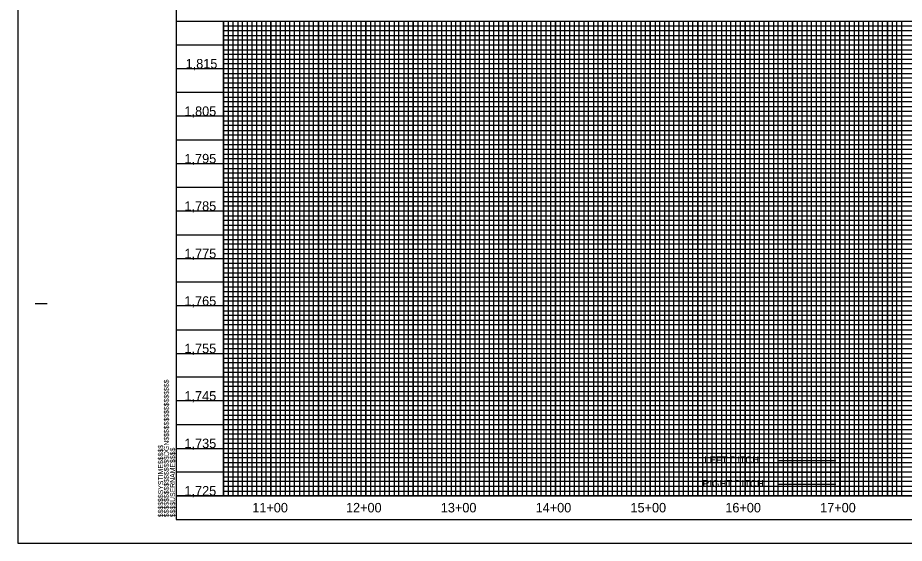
# Model space of a CAD drawing. Extents: x 502400 to 509344, y 448070 to 484209.
# Drawn here: x 505602 to 506537, y 483109 to 483662 of the extents above; entities that cross this region are included whole.
import ezdxf

# ---------------------------------------------------------------- set-up
doc = ezdxf.new("R2010")
doc.units = 0
for name, color, linetype in [('Exist Vertical Profile Vertical Axis Label', 7, 'Continuous'), ('Prop Grid Mask', 7, 'Continuous'), ('Prop PFL Ditch Label CELL', 7, 'Continuous'), ('Prop Vertical Profile Ditch Grade Left', 7, 'Continuous'), ('Sheet Layout Profile Border Port 2', 7, 'Continuous'), ('Sheet Plot Border Outside CELL', 7, 'Continuous'), ('Sheet Profile CELL', 7, 'Continuous'), ('Sheet Profile Grid Major CELL', 7, 'Continuous'), ('Sheet Profile Grid Middle CELL', 7, 'Continuous'), ('Sheet Profile Grid Minor CELL', 7, 'Continuous')]:
    doc.layers.add(name, color=color, linetype=linetype)

msp = doc.modelspace()

# ---------------------------------------------------------------- linework, layer by layer
at = {"layer": 'Prop Grid Mask'}
for points in [[(506319.18, 483208.71), (506469.18, 483208.71), (506469.18, 483183.71), (506319.18, 483183.71)], [(506319.18, 483183.71), (506469.18, 483183.71), (506469.18, 483158.71), (506319.18, 483158.71)]]:
    msp.add_lwpolyline(points, close=True, dxfattribs=at)
at = {"layer": 'Prop PFL Ditch Label CELL'}
for p, q in [((506404.73, 483171.06), (506464.73, 483171.06)), ((506319.18, 483168.71), (506319.18, 483168.71))]:
    msp.add_line(p, q, dxfattribs=at)
at = {"layer": 'Prop Vertical Profile Ditch Grade Left'}
msp.add_line((506404.73, 483196.06), (506464.73, 483196.06), dxfattribs=at)
at = {"layer": 'Sheet Layout Profile Border Port 2'}
msp.add_lwpolyline([(505819.08, 483658.71), (506619.08, 483658.71), (506619.08, 483158.71), (505819.08, 483158.71)], close=True, dxfattribs=at)
at = {"layer": 'Sheet Plot Border Outside CELL'}
msp.add_lwpolyline([(505602.08, 483108.71), (507286.08, 483108.71), (507286.08, 484208.71), (505602.08, 484208.71)], close=True, dxfattribs=at)
at = {"layer": 'Sheet Profile CELL'}
for p, q in [((505769.08, 483658.71), (507269.08, 483658.71)), ((505620.58, 483361.21), (505633.08, 483361.21)), ((507269.08, 483158.71), (505769.08, 483158.71)), ((505769.08, 483133.71), (507269.08, 483133.71)), ((505769.08, 483133.71), (505769.08, 483133.71)), ((505769.08, 483133.71), (505769.08, 483133.71)), ((505769.08, 483133.71), (505769.08, 483133.71)), ((505769.08, 483133.71), (505769.08, 483133.71)), ((505769.08, 483133.71), (505769.08, 483133.71)), ((505769.08, 483133.71), (505769.08, 483133.71)), ((505769.08, 483133.71), (505769.08, 483133.71))]:
    msp.add_line(p, q, dxfattribs=at)
msp.add_lwpolyline([(507269.08, 484183.71), (505769.08, 484183.71), (505769.08, 483133.71), (507269.08, 483133.71)], close=True, dxfattribs=at)
msp.add_lwpolyline([(505806.58, 483133.71), (505806.58, 483133.71)], dxfattribs=at)
at = {"layer": 'Sheet Profile Grid Major CELL'}
for p, q in [((506269.08, 483658.71), (506319.08, 483658.71)), ((506369.08, 483658.71), (506419.08, 483658.71)), ((506469.08, 483658.71), (506519.08, 483658.71))]:
    msp.add_line(p, q, dxfattribs=at)
for points in [[(505769.08, 483658.71), (505769.08, 483158.71), (505819.08, 483158.71), (505819.08, 483658.71), (505869.08, 483658.71), (505869.08, 483158.71), (505919.08, 483158.71), (505919.08, 483658.71), (505969.08, 483658.71), (505969.08, 483158.71), (506019.08, 483158.71), (506019.08, 483658.71), (506069.08, 483658.71), (506069.08, 483158.71), (506119.08, 483158.71), (506119.08, 483658.71), (506169.08, 483658.71), (506169.08, 483158.71), (506219.08, 483158.71), (506219.08, 483658.71), (506269.08, 483658.71), (506269.08, 483158.71), (506319.08, 483158.71), (506319.08, 483658.71), (506369.08, 483658.71), (506369.08, 483158.71), (506419.08, 483158.71), (506419.08, 483658.71), (506469.08, 483658.71), (506469.08, 483158.71), (506519.08, 483158.71), (506519.08, 483658.71), (506569.08, 483658.71)], [(505819.08, 483658.71), (505819.08, 483158.71), (505869.08, 483158.71), (505869.08, 483658.71), (505919.08, 483658.71), (505919.08, 483158.71), (505969.08, 483158.71), (505969.08, 483658.71), (506019.08, 483658.71), (506019.08, 483158.71), (506069.08, 483158.71), (506069.08, 483658.71), (506119.08, 483658.71), (506119.08, 483158.71), (506169.08, 483158.71), (506169.08, 483658.71), (506219.08, 483658.71), (506219.08, 483158.71), (506269.08, 483158.71), (506269.08, 483658.71), (506319.08, 483658.71), (506319.08, 483158.71), (506369.08, 483158.71), (506369.08, 483658.71), (506419.08, 483658.71), (506419.08, 483158.71), (506469.08, 483158.71), (506469.08, 483658.71), (506519.08, 483658.71), (506519.08, 483158.71), (506569.08, 483158.71)], [(507269.08, 483608.71), (505769.08, 483608.71)], [(507269.08, 483558.71), (505769.08, 483558.71), (505769.08, 483508.71), (507269.08, 483508.71)], [(507269.08, 483458.71), (505769.08, 483458.71), (505769.08, 483408.71), (507269.08, 483408.71)], [(507269.08, 483358.71), (505769.08, 483358.71), (505769.08, 483308.71), (507269.08, 483308.71)], [(507269.08, 483258.71), (505769.08, 483258.71), (505769.08, 483258.71), (505769.08, 483208.71), (507269.08, 483208.71)], [(507269.08, 483158.71), (505769.08, 483158.71)]]:
    msp.add_lwpolyline(points, dxfattribs=at)
at = {"layer": 'Sheet Profile Grid Middle CELL'}
for points in [[(505794.08, 483658.71), (505844.08, 483658.71), (505844.08, 483158.71), (505894.08, 483158.71), (505894.08, 483658.71), (505944.08, 483658.71), (505944.08, 483158.71), (505994.08, 483158.71), (505994.08, 483658.71), (506044.08, 483658.71), (506044.08, 483158.71), (506094.08, 483158.71), (506094.08, 483658.71), (506144.08, 483658.71), (506144.08, 483158.71), (506194.08, 483158.71), (506194.08, 483658.71), (506244.08, 483658.71), (506244.08, 483158.71), (506294.08, 483158.71), (506294.08, 483658.71), (506344.08, 483658.71), (506344.08, 483158.71), (506394.08, 483158.71), (506394.08, 483158.71), (506394.08, 483658.71), (506444.08, 483658.71), (506444.08, 483158.71), (506494.08, 483158.71), (506494.08, 483658.71), (506544.08, 483658.71)], [(505769.08, 483633.71), (507269.08, 483633.71)], [(507269.08, 483583.71), (505769.08, 483583.71), (505769.08, 483533.71), (507269.08, 483533.71)], [(507269.08, 483483.71), (505769.08, 483483.71), (505769.08, 483433.71), (507269.08, 483433.71)], [(507269.08, 483383.71), (505769.08, 483383.71), (505769.08, 483333.71), (507269.08, 483333.71)], [(507269.08, 483283.71), (505769.08, 483283.71), (505769.08, 483233.71), (507269.08, 483233.71)], [(507269.08, 483183.71), (505769.08, 483183.71)]]:
    msp.add_lwpolyline(points, dxfattribs=at)
at = {"layer": 'Sheet Profile Grid Minor CELL'}
for p, q in [((505819.08, 483653.71), (507219.08, 483653.71)), ((507219.08, 483648.71), (505819.08, 483648.71)), ((505819.08, 483643.71), (507219.08, 483643.71)), ((507219.08, 483638.71), (505819.08, 483638.71)), ((505819.08, 483628.71), (507219.08, 483628.71)), ((507219.08, 483623.71), (505819.08, 483623.71)), ((505819.08, 483618.71), (507219.08, 483618.71)), ((507219.08, 483613.71), (505819.08, 483613.71)), ((505819.08, 483603.71), (507219.08, 483603.71)), ((507219.08, 483598.71), (505819.08, 483598.71)), ((505819.08, 483593.71), (507219.08, 483593.71)), ((507219.08, 483588.71), (505819.08, 483588.71)), ((505819.08, 483578.71), (507219.08, 483578.71)), ((507219.08, 483573.71), (505819.08, 483573.71)), ((505819.08, 483568.71), (507219.08, 483568.71)), ((507219.08, 483563.71), (505819.08, 483563.71)), ((505819.08, 483553.71), (507219.08, 483553.71)), ((507219.08, 483548.71), (505819.08, 483548.71)), ((505819.08, 483543.71), (507219.08, 483543.71)), ((507219.08, 483538.71), (505819.08, 483538.71)), ((505819.08, 483528.71), (507219.08, 483528.71)), ((507219.08, 483523.71), (505819.08, 483523.71)), ((505819.08, 483518.71), (507219.08, 483518.71)), ((507219.08, 483513.71), (505819.08, 483513.71)), ((505819.08, 483503.71), (507219.08, 483503.71)), ((507219.08, 483498.71), (505819.08, 483498.71)), ((505819.08, 483493.71), (507219.08, 483493.71)), ((507219.08, 483488.71), (505819.08, 483488.71)), ((505819.08, 483478.71), (507219.08, 483478.71)), ((507219.08, 483473.71), (505819.08, 483473.71)), ((505819.08, 483468.71), (507219.08, 483468.71)), ((507219.08, 483463.71), (505819.08, 483463.86)), ((505819.08, 483453.71), (507219.08, 483453.71)), ((507219.08, 483448.71), (505819.08, 483448.71)), ((505819.08, 483443.71), (507219.08, 483443.71)), ((507219.08, 483438.71), (505819.08, 483438.71)), ((505819.08, 483428.71), (507219.08, 483428.71)), ((507219.08, 483423.71), (505819.08, 483423.71)), ((505819.08, 483418.71), (507219.08, 483418.71)), ((507219.08, 483413.71), (505819.08, 483413.71)), ((505819.08, 483403.71), (507219.08, 483403.71)), ((507219.08, 483398.71), (505819.08, 483398.71)), ((505819.08, 483393.71), (507219.08, 483393.71)), ((507219.08, 483388.71), (505819.08, 483388.71)), ((505819.08, 483378.71), (507219.08, 483378.71)), ((507219.08, 483373.71), (505819.08, 483373.71)), ((505819.08, 483368.71), (507219.08, 483368.71)), ((507219.08, 483363.71), (505819.08, 483363.71)), ((505819.08, 483353.71), (507219.08, 483353.71)), ((507219.08, 483348.71), (505819.08, 483348.71)), ((505819.08, 483343.71), (507219.08, 483343.71)), ((507219.08, 483338.71), (505819.08, 483338.71)), ((505819.08, 483328.71), (507219.08, 483328.71)), ((507219.08, 483323.71), (505819.08, 483323.71)), ((505819.08, 483318.71), (507219.08, 483318.71)), ((507219.08, 483313.71), (505819.08, 483313.71)), ((505819.08, 483303.71), (507219.08, 483303.71)), ((507219.08, 483298.71), (505819.08, 483298.71)), ((505819.08, 483293.71), (507219.08, 483293.71)), ((507219.08, 483288.71), (505819.08, 483288.71)), ((505819.08, 483278.71), (507219.08, 483278.71)), ((507219.08, 483273.71), (505819.08, 483273.71)), ((505819.08, 483268.71), (507219.08, 483268.71)), ((507219.08, 483263.71), (505819.08, 483263.71)), ((505819.08, 483253.71), (507219.08, 483253.71)), ((507219.08, 483248.71), (505819.08, 483248.71)), ((505819.08, 483243.71), (507219.08, 483243.71)), ((507219.08, 483238.71), (505819.08, 483238.71)), ((505819.08, 483228.71), (507219.08, 483228.71)), ((507219.08, 483223.71), (505819.08, 483223.71)), ((505819.08, 483218.71), (507219.08, 483218.71)), ((507219.08, 483213.71), (505819.08, 483213.71)), ((505819.08, 483203.71), (507219.08, 483203.71)), ((507219.08, 483198.71), (505819.08, 483198.71)), ((505819.08, 483193.71), (507219.08, 483193.71)), ((507219.08, 483188.71), (505819.08, 483188.71)), ((505819.08, 483178.71), (507219.08, 483178.71)), ((507219.08, 483173.71), (505819.08, 483173.71)), ((505819.08, 483168.71), (507219.08, 483168.71)), ((505819.08, 483163.71), (507219.08, 483163.71))]:
    msp.add_line(p, q, dxfattribs=at)
for points in [[(505819.08, 483658.71), (505824.08, 483658.71), (505824.08, 483158.71), (505829.08, 483158.71), (505829.08, 483658.71), (505834.08, 483658.71), (505834.08, 483158.71), (505839.08, 483158.71), (505839.08, 483658.71), (505849.08, 483658.71), (505849.08, 483158.71), (505854.08, 483158.71), (505854.08, 483658.71), (505859.08, 483658.71), (505859.08, 483158.71), (505864.08, 483158.71), (505874.08, 483158.71), (505879.08, 483158.71), (505879.08, 483658.71), (505884.08, 483658.71), (505884.08, 483158.71), (505889.08, 483158.71), (505889.08, 483658.71), (505899.08, 483658.71), (505899.08, 483158.71), (505904.08, 483158.71), (505904.08, 483658.71), (505909.08, 483658.71), (505909.08, 483158.71), (505914.08, 483158.71), (505914.08, 483658.71), (505924.08, 483658.71), (505924.08, 483158.71), (505929.08, 483158.71), (505929.08, 483658.71), (505934.08, 483658.71), (505934.08, 483158.71), (505939.08, 483158.71), (505939.08, 483658.71), (505949.08, 483658.71), (505949.08, 483158.71), (505954.08, 483158.71), (505954.08, 483658.71), (505959.08, 483658.71), (505959.08, 483158.71), (505964.08, 483158.71), (505964.08, 483658.71), (505974.08, 483658.71), (505974.08, 483158.71), (505979.08, 483158.71), (505979.08, 483658.71), (505984.08, 483658.71), (505984.08, 483158.71), (505989.08, 483158.71), (505989.08, 483658.71), (505999.08, 483658.71), (505999.08, 483158.71), (506004.08, 483158.71), (506004.08, 483658.71), (506009.08, 483658.71), (506009.08, 483158.71), (506014.08, 483158.71), (506014.08, 483658.71), (506024.08, 483658.71), (506024.08, 483158.71), (506029.08, 483158.71), (506029.08, 483658.71), (506034.08, 483658.71), (506034.08, 483158.71)], [(505864.08, 483158.71), (505864.08, 483658.71), (505874.08, 483658.71), (505874.08, 483158.71)], [(506034.08, 483158.71), (506039.08, 483158.71), (506039.08, 483658.71), (506049.08, 483658.71), (506049.08, 483158.71), (506054.08, 483158.71), (506054.08, 483658.71), (506059.08, 483658.71), (506059.08, 483158.71), (506064.08, 483158.71), (506064.08, 483658.71), (506074.08, 483658.71), (506074.08, 483158.71), (506079.08, 483158.71), (506079.08, 483658.71), (506084.08, 483658.71), (506084.08, 483158.71), (506089.08, 483158.71), (506089.08, 483658.71), (506099.08, 483658.71), (506099.08, 483158.71), (506104.08, 483158.71), (506104.08, 483658.71), (506109.08, 483658.71), (506109.08, 483158.71), (506114.08, 483158.71), (506114.08, 483658.71), (506124.08, 483658.71), (506124.08, 483158.71), (506129.08, 483158.71), (506129.08, 483658.71), (506134.08, 483658.71), (506134.08, 483158.71), (506139.08, 483158.71), (506139.08, 483658.71), (506149.08, 483658.71), (506149.08, 483158.71), (506154.08, 483158.71), (506154.08, 483658.71), (506159.08, 483658.71), (506159.08, 483158.71), (506164.08, 483158.71), (506164.08, 483658.71), (506174.08, 483658.71), (506174.08, 483158.71), (506179.08, 483158.71), (506179.08, 483658.71), (506184.08, 483658.71), (506184.08, 483158.71), (506189.08, 483158.71), (506189.08, 483658.71), (506199.08, 483658.71), (506199.08, 483158.71), (506204.08, 483158.71), (506204.08, 483658.71), (506209.08, 483658.71), (506209.08, 483158.71), (506214.08, 483158.71), (506214.08, 483658.71), (506224.08, 483658.71), (506224.08, 483158.71), (506229.08, 483158.71), (506229.08, 483658.71), (506234.08, 483658.71), (506234.08, 483158.71), (506239.08, 483158.71), (506239.08, 483658.71), (506249.08, 483658.71), (506249.08, 483158.71), (506254.08, 483158.71), (506254.08, 483658.71), (506259.08, 483658.71), (506259.08, 483158.71), (506264.08, 483158.71), (506264.08, 483658.71), (506274.08, 483658.71), (506274.08, 483158.71), (506279.08, 483158.71), (506279.08, 483658.71), (506284.08, 483658.71), (506284.08, 483158.71), (506289.08, 483158.71), (506289.08, 483658.71), (506299.08, 483658.71), (506299.08, 483158.71), (506304.08, 483158.71), (506304.08, 483658.71), (506309.08, 483658.71), (506309.08, 483158.71), (506314.08, 483158.71), (506314.08, 483658.71), (506324.08, 483658.71), (506324.08, 483158.71), (506329.08, 483158.71), (506329.08, 483658.71), (506334.08, 483658.71), (506334.08, 483158.71), (506339.08, 483158.71), (506339.08, 483658.71), (506349.08, 483658.71)], [(506349.08, 483658.71), (506349.08, 483158.71), (506354.08, 483158.71), (506354.08, 483658.71), (506359.08, 483658.71), (506359.08, 483158.71), (506364.08, 483158.71), (506364.08, 483658.71), (506374.08, 483658.71), (506374.08, 483158.71), (506379.08, 483158.71), (506379.08, 483658.71), (506384.08, 483658.71), (506384.08, 483158.71), (506389.08, 483158.71), (506389.08, 483658.71), (506399.08, 483658.71), (506399.08, 483158.71), (506404.08, 483158.71), (506404.08, 483658.71), (506409.08, 483658.71), (506409.08, 483158.71), (506414.08, 483158.71), (506414.08, 483658.71), (506424.08, 483658.71), (506424.08, 483158.71), (506429.08, 483158.71), (506429.08, 483658.71), (506434.08, 483658.71), (506434.08, 483158.71), (506439.08, 483158.71), (506439.08, 483658.71), (506449.08, 483658.71), (506449.08, 483158.71), (506454.08, 483158.71), (506454.08, 483658.71), (506459.08, 483658.71), (506459.08, 483158.71), (506464.08, 483158.71), (506464.08, 483658.71), (506474.08, 483658.71), (506474.08, 483158.71), (506474.08, 483158.71), (506479.08, 483158.71), (506479.08, 483658.71), (506484.08, 483658.71), (506484.08, 483158.71), (506489.08, 483158.71), (506489.08, 483658.71), (506499.08, 483658.71), (506499.08, 483158.71), (506504.08, 483158.71), (506504.08, 483658.71), (506509.08, 483658.71), (506509.08, 483158.71), (506514.08, 483158.71), (506514.08, 483658.71), (506524.08, 483658.71), (506524.08, 483158.71), (506529.08, 483158.71), (506529.08, 483658.71), (506534.08, 483658.71), (506534.08, 483158.71), (506539.08, 483158.71)]]:
    msp.add_lwpolyline(points, dxfattribs=at)

# ---------------------------------------------------------------- texts
at = {"layer": 'Exist Vertical Profile Vertical Axis Label'}
for s, p in [('1,815', (505779.13, 483608.96)), ('1,805', (505777.93, 483558.96)), ('1,795', (505777.93, 483508.96)), ('1,785', (505777.93, 483458.96)), ('1,775', (505777.93, 483408.96)), ('1,765', (505777.93, 483358.96)), ('1,755', (505777.93, 483308.96)), ('1,745', (505777.93, 483258.96)), ('1,735', (505777.93, 483208.96)), ('1,725', (505777.93, 483158.96)), ('11+00', (505849.41, 483141.21)), ('12+00', (505948.21, 483141.21)), ('13+00', (506048.21, 483141.21)), ('14+00', (506148.21, 483141.21)), ('15+00', (506248.21, 483141.21)), ('16+00', (506348.21, 483141.21)), ('17+00', (506448.21, 483141.21))]:
    msp.add_text(s, height=10, dxfattribs=at).set_placement(p)
at = {"layer": 'Prop PFL Ditch Label CELL'}
msp.add_text('RIGHT DITCH', height=7.485, dxfattribs=at).set_placement((506324.18, 483167.81))
at = {"layer": 'Prop Vertical Profile Ditch Grade Left'}
msp.add_text('LEFT DITCH', height=7.485, dxfattribs=at).set_placement((506326.01, 483192.81))
at = {"layer": 'Sheet Profile CELL'}
for s, p in [('$$$$$$$$$$$$$$$$DGN$$$$$$$$$$$$$$$$', (505761.44, 483136.09)), ('$$$$$$SYSTIME$$$$$', (505755.39, 483136.09)), ('$$$$USERNAME$$$$', (505768.02, 483136.1))]:
    msp.add_text(s, height=5.25, rotation=90, dxfattribs=at).set_placement(p)

doc.saveas('drawing.dxf')
